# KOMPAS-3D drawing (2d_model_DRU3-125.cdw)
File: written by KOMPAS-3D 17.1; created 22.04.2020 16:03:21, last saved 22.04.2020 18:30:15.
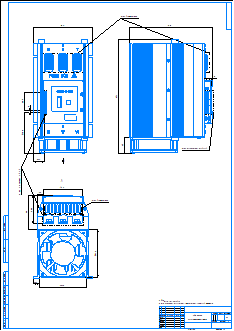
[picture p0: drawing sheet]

Sheet 1: A1, portrait

Title block, sheet 1: name: DRU3-125 / Габаритный чертеж; sheets: 1; sheet format: A1; stored path: E:\Марк\DRU3\DRU3-XX\2d_model_DRU3-200.cdw

Views: Вид по стрелке 4
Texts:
  Пользователь Windows
  ·зЙИ
  НвїЗЈЁ7.27Ј©
  ИэПаЅУПЯ¶ЛЧУ
  ЛДПаЅУПЯ¶ЛЧУ
  РЎПЯВ·°еЈЁ0Ј©
  Гж°еЧйєП(7.27)
  ВЭДё
  M4ВЭЛї
  ВЭДёС№Ж¬
  ВЭЛї
  µжЖ¬
  M8ВЭЛїЧйєП
  M4ВЭЛї(0)
  M3-10ЖЅН·ВЭЛї
  M3ВЭЛї(0)
  M4ВЭЛї(і¤)
Dimensions and other numbers on the sheet: 1:1; 1; 200AЙўИИЖч(0); 200AІа°е(0); 200AЦ§јЬ(0); 200AєуёЗ(1); 200AHHT3µчЅЪїЄ№ШPCB(0); 200AєуёЗ(0); 200AИэПаµзБ¦µчХыЖч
